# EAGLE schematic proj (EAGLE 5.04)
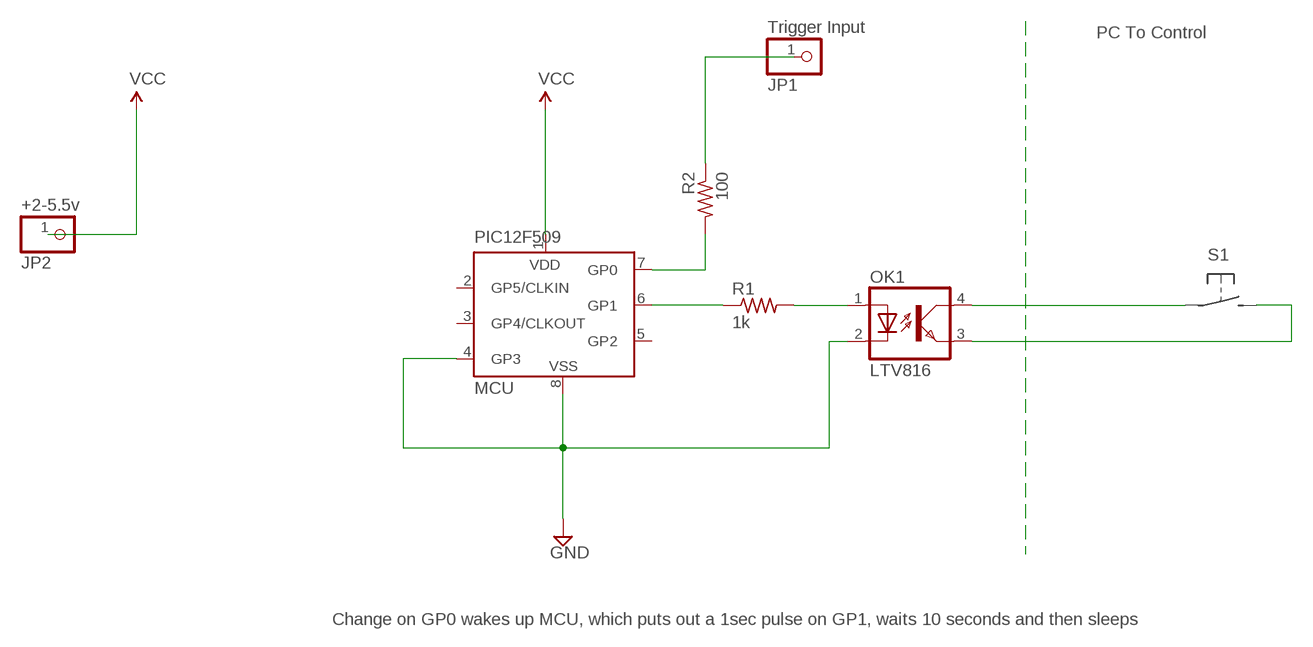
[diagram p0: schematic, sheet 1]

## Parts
JP1  Trigger Input  PINHD-1X1  [1X01]
JP2  +2-5.5v  PINHD-1X1  [1X01]
OK1  LTV816  [DIL04]
PIC12F509  MCU  PIC12F629P  [DIL8]
R1  1k  R-US_0204/5  [0204/5]
R2  100  R-US_0204/5  [0204/5]

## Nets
GND: OK1.2(C) PIC12F509.4(GP3) PIC12F509.8(VSS)
N$2: PIC12F509.6(GP1) R1.1
N$3: OK1.1(A) R1.2
N$4: PIC12F509.7(GP0) R2.2
N$5: JP1.1 R2.1
N$6: OK1.4(COL)
N$7: OK1.3(EMIT)
VCC: JP2.1 PIC12F509.1(VDD)
Unconnected: PIC12F509.2(GP5/CLKIN) PIC12F509.3(GP4/CLKOUT) PIC12F509.5(GP2)

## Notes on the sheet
- PC To Control
- Change on GP0 wakes up MCU, which puts out a 1sec pulse on GP1, waits 10 seconds and then sleeps

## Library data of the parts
JP1 JP2 = pinhead:PINHD-1X1: PIN HEADER
OK1 = optocoupler:LTV816: OPTO COUPLER Source: LITEON, LTV816.pdf
PIC12F509 = microchip:PIC12F6*: Data Sheet 8-Pin FLASH-Based 8-Bit CMOS Microcontrollers Source: http://www.microchip.com .. 41190c.pdf
R1 R2 = resistor:R-US_: RESISTOR, American symbol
